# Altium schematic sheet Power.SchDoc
size 292 x 193 mm; Author: Power Lin; DocumentNumber: 4; SheetNumber: 4; SheetTotal: 4; Website: wiki-power.com
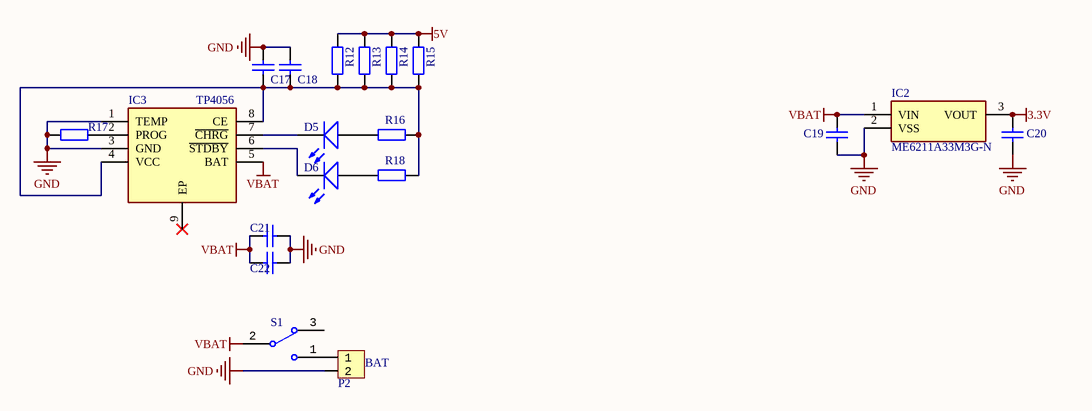
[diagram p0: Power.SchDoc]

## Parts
C17  10nF  [CAP-0603]  (value not drawn)
C18  100nF  [CAP-0603]  (value not drawn)
C19  1uF  [CAP-0603]  (value not drawn)
C20  1uF  [CAP-0603]  (value not drawn)
C21  100nF  [CAP-0603]  (value not drawn)
C22  10nF  [CAP-0603]  (value not drawn)
D5  RED  [LED-0603]  (value not drawn)
D6  RED  [LED-0603]  (value not drawn)
IC2  ME6211A33M3G-N  [SOT-23-3]
IC3  TP4056  [MSOP_E120_P0.5_10]
P2  HDR1x2_2.54  [HDR1X2_2.54_90]  (value not drawn)
R12  1R  [R-0603]  (value not drawn)
R13  1R  [R-0603]  (value not drawn)
R14  1R  [R-0603]  (value not drawn)
R15  1R  [R-0603]  (value not drawn)
R16  2K  [R-0603]  (value not drawn)
R17  1.2K  [R-0603]  (value not drawn)
R18  10K  [R-0603]  (value not drawn)
S1  Switch_SPDT  [SwitchSPDT_2.8X6.6_90]  (value not drawn)

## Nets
3.3V: C20.2 IC2.3(VOUT)
5V: R12.2 R13.2 R14.2 R15.2
GND: C17.2 C18.2 C19.1 C20.1 C21.1 C22.1 IC2.2(VSS) IC3.1(TEMP) IC3.3(GND) P2.2 R17.1
VBAT: C19.2 C21.2 C22.2 IC2.1(VIN) IC3.5(BAT) S1.2
NetC17_1: C17.1 C18.1 IC3.4(VCC) IC3.8(CE) R12.1 R13.1 R14.1 R15.1 R16.2 R18.2
NetD5_A: D5.A R16.1
NetD5_K: D5.K IC3.7(~{CHRG})
NetD6_A: D6.A R18.1
NetD6_K: D6.K IC3.6(~{STDBY})
NetIC3_2: IC3.2(PROG) R17.2
NetP2_1: P2.1 S1.1

Not connected (* = marked no-connect by the designer): IC3 9(EP)*; S1 3

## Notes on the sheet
- (near P2) BAT

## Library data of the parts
C17-C22 = CAP: 贴片电容
D5 D6 = LED: 发光二极管; pin to pad: A>1 K>2
IC2 = ME6211A33M3G-N: 线性稳压; Manufacturer_Name: Nexperia; Manufacturer_Part_Number: SI2302DS
IC3 = TP4056: 锂电池充电（1A 线性）; Manufacturer_Name: Nanjing Extension Microelectronics; Manufacturer_Part_Number: TP4056-42-ESOP8
P2 = HDR1x2_2.54: Header
R12-R18 = RES: 贴片电阻
S1 = Switch_SPDT: Value: SPDT 3P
